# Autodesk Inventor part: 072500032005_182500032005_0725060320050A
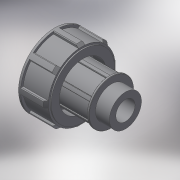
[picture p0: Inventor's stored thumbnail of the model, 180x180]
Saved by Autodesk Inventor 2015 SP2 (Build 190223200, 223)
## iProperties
Created: 2017-04
Part Number: 072500032005_182500032005_0725060320050A
Material: Generic
Description: PLASSON THREADED ADAPTOR 32-1/2"
Document SubType Name: Modeling
Designer: KIM
Density: 1 g/cm^3
Appearance: Default
Author: KIM
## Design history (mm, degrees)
derived "07250.ipt"
feature "Solid1::07250.ipt"
tag "TaggingFeature1"
body "Solid1"
other parameters: "d1" = 20.955, "d2" = 85, "d3" = 17, "d6" = 64, "d7" = 59.52, "d8" = 51.2, "d9" = 32, "d10" = 35.6235, "d12" = 12.573, "d13" = 16.764, "d14" = 19.55, "d15" = 48, "d16" = 2.55, "d17" = 34, "d18" = 17, "d19" = 20.4, "d24" = 4.191, "d25" = 2.0955, "d27" = 0, "d28" = 1.6764, "d31" = 0.4191, "d35" = 360 deg, "d41" = 29.337, "d56" = 35.2, "d57" = 3.2, "d58" = 1.6, "d60" = 0, "d61" = 0.20955, "d64" = 0.20955, "d68" = 360 deg, "d_" = 32, "R_" = 20.955, "E_" = 64, "H_" = 85, "l_2" = 17, "d55" = 32
